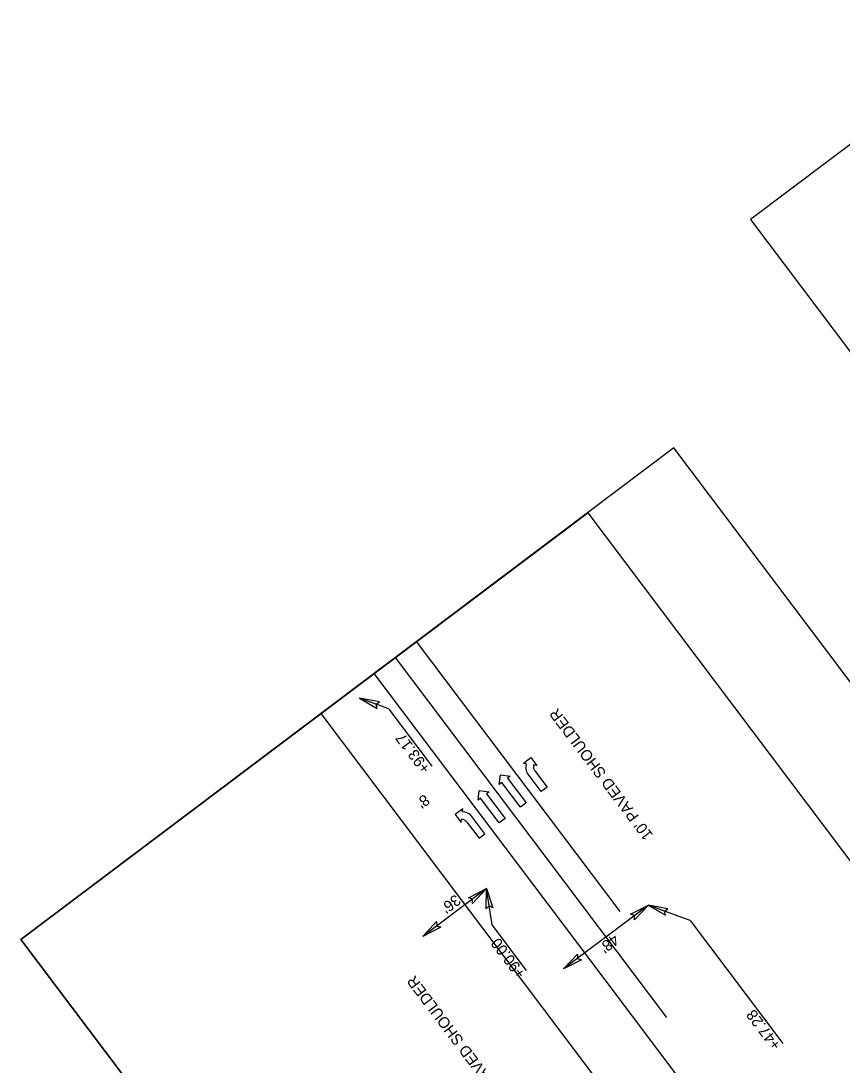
# Model space of a CAD drawing. Extents: x 1262917 to 1264804, y 775326 to 777329.
# Drawn here: x 1263313.4 to 1263684.5, y 776308.6 to 776780.7 of the extents above; entities that cross this region are included whole.
import ezdxf

# ---------------------------------------------------------------- set-up
doc = ezdxf.new("R2010")
doc.units = 0
for name, color, linetype in [('Prop Dimension', 7, 'Continuous'), ('Prop Dimension Text', 7, 'Continuous'), ('Prop Lane Arrow CELL', 7, 'Continuous'), ('Prop Lane Lines', 7, 'Continuous'), ('Prop Terminator CELL', 7, 'Continuous'), ('Scratch_Level_1', 7, 'Continuous'), ('Sheet Typical CELL', 7, 'Continuous')]:
    doc.layers.add(name, color=color, linetype=linetype)

msp = doc.modelspace()

# ---------------------------------------------------------------- linework, layer by layer
at = {"layer": 'Prop Dimension Text'}
for p, q in [((1263479.71, 776469.59), (1263466.48, 776474.44)), ((1263479.74, 776469.54), (1263499.14, 776443.78)), ((1263523.77, 776388.4), (1263495.02, 776366.74)), ((1263526.38, 776371.99), (1263523.77, 776388.4)), ((1263596.99, 776380.95), (1263558.65, 776352.07)), ((1263615.8, 776373.98), (1263596.8, 776380.95)), ((1263541.91, 776351.38), (1263526.38, 776371.99)), ((1263615.8, 776373.98), (1263657.73, 776318.31))]:
    msp.add_line(p, q, dxfattribs=at)
at = {"layer": 'Prop Lane Arrow CELL'}
for p, q in [((1263540.32, 776444.98), (1263543.81, 776447.67)), ((1263541.79, 776444.77), (1263540.32, 776444.98)), ((1263543.81, 776447.67), (1263546.56, 776444.1)), ((1263548.54, 776432.33), (1263542.19, 776440.75)), ((1263546.56, 776444.1), (1263545.09, 776444.31)), ((1263545.67, 776441.62), (1263551.18, 776434.31)), ((1263529.49, 776435.5), (1263530.07, 776439.89)), ((1263530.69, 776436.41), (1263529.49, 776435.5)), ((1263530.07, 776439.89), (1263534.52, 776439.29)), ((1263539.11, 776425.22), (1263530.69, 776436.41)), ((1263534.52, 776439.29), (1263533.33, 776438.39)), ((1263533.33, 776438.39), (1263541.75, 776427.21)), ((1263519.96, 776428.33), (1263520.54, 776432.71)), ((1263520.54, 776432.71), (1263524.99, 776432.12)), ((1263524.99, 776432.12), (1263523.8, 776431.21)), ((1263523.8, 776431.21), (1263532.22, 776420.03)), ((1263551.18, 776434.31), (1263548.54, 776432.33)), ((1263521.16, 776429.23), (1263519.96, 776428.33)), ((1263529.58, 776418.05), (1263521.16, 776429.23)), ((1263541.75, 776427.21), (1263539.11, 776425.22)), ((1263513.15, 776424.51), (1263509.61, 776421.91)), ((1263509.61, 776421.91), (1263512.28, 776418.28)), ((1263512.95, 776423.04), (1263513.15, 776424.51)), ((1263523.05, 776413.12), (1263516.7, 776421.55)), ((1263512.28, 776418.28), (1263512.48, 776419.75)), ((1263514.91, 776418.45), (1263520.41, 776411.14)), ((1263532.22, 776420.03), (1263529.58, 776418.05)), ((1263520.41, 776411.14), (1263523.05, 776413.12))]:
    msp.add_line(p, q, dxfattribs=at)
for centre, radius, start, end in [((1263546.8, 776443.23), 5.25, 162.9996, 208.3113), ((1263548.27, 776443.59), 3.27, 167.3292, 216.9874), ((1263513.04, 776417.8), 5.25, 45.6635, 90.9752), ((1263512.3, 776416.49), 3.27, 36.9874, 86.6456)]:
    msp.add_arc(centre, radius, start, end, dxfattribs=at)
at = {"layer": 'Prop Lane Lines'}
for p, q in [((1263584.16, 776378.04), (1263492.24, 776500.08)), ((1263605.23, 776330.12), (1263482.65, 776492.86)), ((1263564.99, 776363.6), (1263473.07, 776485.64)), ((1263657.37, 776191.08), (1263449.1, 776467.59)), ((1263797.93, 776054.33), (1263564.99, 776363.6))]:
    msp.add_line(p, q, dxfattribs=at)
at = {"layer": 'Prop Terminator CELL'}
for points in [[(1263475.47, 776472.79), (1263466.48, 776474.44), (1263474.43, 776469.82), (1263473.9, 776471.72)], [(1263515.65, 776384.23), (1263523.77, 776388.4), (1263517.5, 776381.68), (1263517.46, 776383.65)], [(1263523.61, 776379.27), (1263523.77, 776388.4), (1263526.73, 776379.7), (1263524.97, 776380.59)], [(1263588.87, 776376.78), (1263596.99, 776380.95), (1263590.72, 776374.23), (1263590.68, 776376.2)], [(1263605.78, 776379.31), (1263596.8, 776380.95), (1263604.74, 776376.33), (1263604.22, 776378.23)], [(1263503.14, 776370.92), (1263495.02, 776366.74), (1263501.28, 776373.47), (1263501.33, 776371.5)], [(1263566.77, 776356.25), (1263558.65, 776352.07), (1263564.91, 776358.8), (1263564.96, 776356.83)]]:
    msp.add_lwpolyline(points, close=True, dxfattribs=at)
at = {"layer": 'Scratch_Level_1'}
msp.add_lwpolyline([(1263815.66, 775698.62), (1263313.44, 776365.4), (1263569.52, 776558.29), (1264071.75, 775891.5)], close=True, dxfattribs=at)
at = {"layer": 'Sheet Typical CELL'}
for points in [[(1264496.08, 776206.58), (1263954.62, 776925.45), (1263643.13, 776690.84), (1264184.59, 775971.97)], [(1263313.44, 776365.4), (1263815.66, 775698.62), (1264110.72, 775920.86), (1263608.5, 776587.64)]]:
    msp.add_lwpolyline(points, close=True, dxfattribs=at)

# ---------------------------------------------------------------- texts
at = {"layer": 'Prop Dimension'}
for s, p in [("10' PAVED SHOULDER", (1263599.28, 776412.63)), ('+93.17', (1263498.73, 776442.78)), ('+90.00', (1263541.79, 776350.09)), ("10' PAVED SHOULDER", (1263534.88, 776291.83)), ('+47.28', (1263657.16, 776317.75))]:
    msp.add_text(s, height=5, rotation=126.9874, dxfattribs=at).set_placement(p)
at = {"layer": 'Prop Dimension Text'}
for s, p in [("8'", (1263495.7, 776431.27)), ("36'", (1263509.75, 776386)), ("48'", (1263581.34, 776368.1))]:
    msp.add_text(s, height=5, rotation=216.9874, dxfattribs=at).set_placement(p)

doc.saveas('drawing.dxf')
